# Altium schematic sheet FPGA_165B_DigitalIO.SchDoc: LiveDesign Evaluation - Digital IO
size B; Organization: Altium Limited; Address1: L3, 12a Rodborough Rd; Address2: Frenchs Forest; Address3: NSW; Address4: Australia 2086
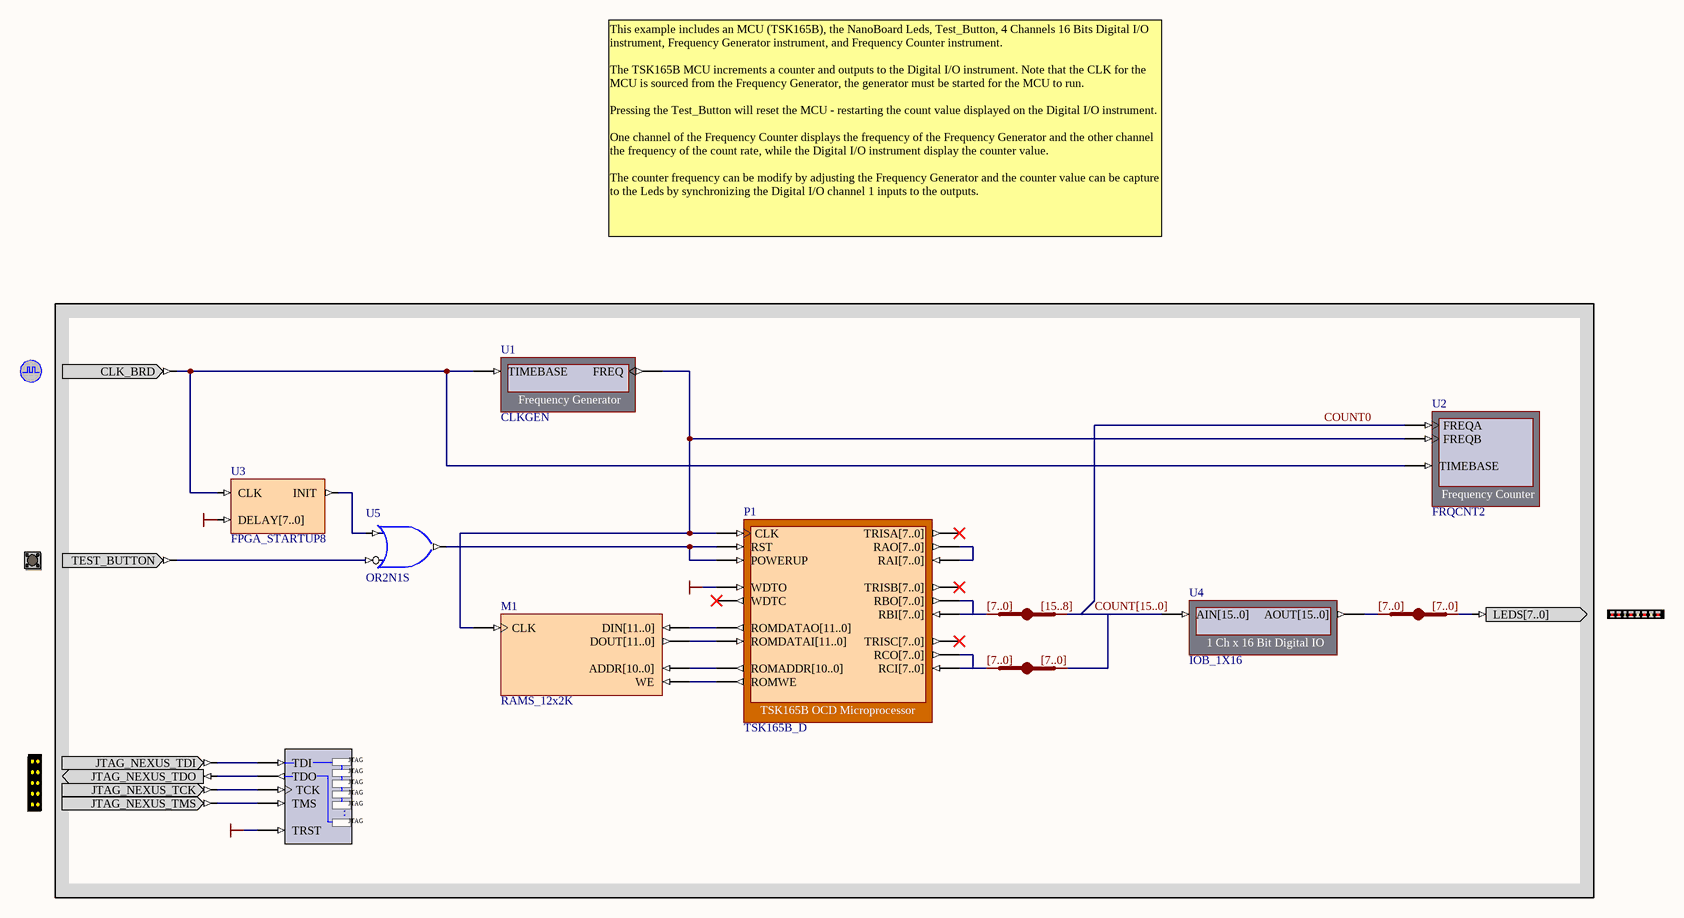
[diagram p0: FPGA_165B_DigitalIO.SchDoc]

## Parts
CLOCK_BOARD  CLOCK_BOARD  (value not drawn)
JB_AUTO1  IndexA: [7..0]  IndexB: [15..8]  (hidden comment: JB)
JB_AUTO2  IndexA: [7..0]  (hidden comment: JB)
JB_AUTO3  IndexA: [7..0]  (hidden comment: JB)
LED  LED  (value not drawn)
M1  RAMS_12x2K
NEXUS_JTAG_CONNECTOR  NEXUS_JTAG_CONNECTOR  (value not drawn)
NEXUS_JTAG_PORT  NEXUS_JTAG_PORT  (value not drawn)
P1  TSK165B_D
TEST_BUTTON  TEST_BUTTON  (value not drawn)
U1  CLKGEN
U2  FRQCNT2
U3  FPGA_STARTUP8
U4  IOB_1X16
U5  OR2N1S

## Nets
GND: P1.WDTO
VCC: NEXUS_JTAG_PORT.TRST
VCCBUS[..]: U3.DELAY[7..0]
COUNT0: U2.FREQA
NetCLOCK_BOARD_CLK_BRD: CLOCK_BOARD.CLK_BRD U1.TIMEBASE U2.TIMEBASE U3.CLK
NetM1_CLK: M1.CLK P1.CLK U1.FREQ U2.FREQB
NetM1_WE: M1.WE P1.ROMWE
NetNEXUS_JTAG_CONNECTOR_JTAG_NEXUS_TCK: NEXUS_JTAG_CONNECTOR.JTAG_NEXUS_TCK NEXUS_JTAG_PORT.TCK
NetNEXUS_JTAG_CONNECTOR_JTAG_NEXUS_TDI: NEXUS_JTAG_CONNECTOR.JTAG_NEXUS_TDI NEXUS_JTAG_PORT.TDI
NetNEXUS_JTAG_CONNECTOR_JTAG_NEXUS_TDO: NEXUS_JTAG_CONNECTOR.JTAG_NEXUS_TDO NEXUS_JTAG_PORT.TDO
NetNEXUS_JTAG_CONNECTOR_JTAG_NEXUS_TMS: NEXUS_JTAG_CONNECTOR.JTAG_NEXUS_TMS NEXUS_JTAG_PORT.TMS
NetP1_POWERUP: P1.POWERUP P1.RST U5.O
NetTEST_BUTTON_TEST_BUTTON: TEST_BUTTON.TEST_BUTTON U5.I0
NetU3_INIT: U3.INIT U5.I1

Not connected (* = marked no-connect by the designer): JB_AUTO1 A[0..0] B[0..0]; JB_AUTO2 A[0..0] B[0..0]; JB_AUTO3 A[0..0] B[0..0]; LED LEDS[7..0]; M1 ADDR[10..0] DIN[11..0] DOUT[11..0]; P1 RAI[7..0] RAO[7..0] RBI[7..0] RBO[7..0] RCI[7..0] RCO[7..0] ROMADDR[10..0] ROMDATAI[11..0] ROMDATAO[11..0] TRISA[7..0]* TRISB[7..0]* TRISC[7..0]* WDTC*; U4 AIN[15..0] AOUT[15..0]

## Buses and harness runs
bus COUNT[15..0]

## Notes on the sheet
- This example includes an MCU (TSK165B), the NanoBoard Leds, Test_Button, 4 Channels 16 Bits Digital I/O instrument, Frequency Generator instrument, and Frequency Counter instrument.
  The TSK165B MCU increments a counter and outputs to the Digital I/O instrument. Note that the CLK for the MCU is sourced from the Frequency Generator, the generator must be started for the MCU to run.
  Pressing the Test_Button will reset the MCU - restarting the count value displayed on the Digital I/O instrument.
  One channel of the Frequency Counter displays the frequency of the Frequency Generator and the other channel the frequency of the count rate, while the Digital I/O instrument display the counter value.
  The counter frequency can be modify by adjusting the Frequency Generator and the counter value can be capture to the Leds by synchronizing the Digital I/O channel 1 inputs to the outputs.

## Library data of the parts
CLOCK_BOARD = CLOCK_BOARD: Global System Clock Supply; PortComponent: True
JB_AUTO1-JB_AUTO3 = JB: System BUS Joiner
LED = LED: 8-Way LEDS; PortComponent: True
M1 = RAMS_12x2K: Single Port RAM; Memory_Depth: 2048; Memory_Type: RAM_SinglePortBlock; Memory_Width: 12; Memory_ClockEdge: Rising; Nexus_Core: Memory_Program; Memory_EnablePin: False
NEXUS_JTAG_CONNECTOR = NEXUS_JTAG_CONNECTOR: JTAG Port; PortComponent: True
NEXUS_JTAG_PORT = NEXUS_JTAG_PORT: Soft Nexus-Chain Connector; NEXUS_JTAG_CONNECTOR: True
P1 = TSK165B_D: TSK165B OCD Microprocessor; NEXUS_CORE: Processor_OCDS; NEXUS_JTAG_DEVICE: True; NEXUS_JTAG_ORDER: 0; ChildModel1: TSK165B_D_RAM128x8; ChildCore1: M1
TEST_BUTTON = TEST_BUTTON: Test Button; PortComponent: True
U1 = CLKGEN: Frequency Generator; NEXUS_CORE: Instrument; NEXUS_JTAG_DEVICE: True; NEXUS_JTAG_ORDER: 0
U2 = FRQCNT2: Frequency Counter; NEXUS_CORE: Instrument; NEXUS_JTAG_DEVICE: True; NEXUS_JTAG_ORDER: 0
U3 = FPGA_STARTUP8: FPGA Startup With 8 Bit Delay
U4 = IOB_1X16: 1 Ch x 16 Bit Digital IO; NEXUS_CORE: Instrument; NEXUS_JTAG_DEVICE: True; NEXUS_JTAG_ORDER: 0
U5 = OR2N1S: 2-Input OR Gate with Active Low A Input, Single Pin Version; Xilinx Equivalent: OR2B1; ArchiveName: GENERIC; VHDLIB_SIM: GENERIC_LIB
